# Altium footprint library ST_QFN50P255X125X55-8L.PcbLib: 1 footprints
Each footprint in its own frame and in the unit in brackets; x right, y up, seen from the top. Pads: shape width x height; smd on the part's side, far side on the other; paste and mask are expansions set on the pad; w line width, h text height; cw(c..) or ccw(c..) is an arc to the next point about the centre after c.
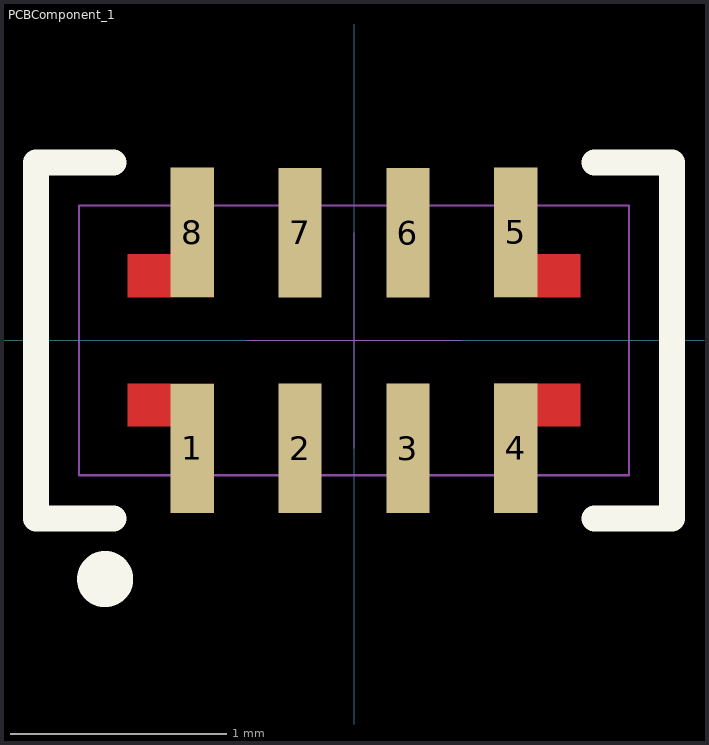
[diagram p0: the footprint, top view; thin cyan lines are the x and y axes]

## PCBComponent_1 [mm]
pads (8):
  rect 0.2x0.6 smd paste-20 mask+0.025: 1(-0.75,-0.501) 2(-0.25,-0.5) 3(0.25,-0.5) 4(0.75,-0.5) 5(0.75,0.5) 6(0.25,0.5) 7(-0.25,0.5) 8(-0.75,0.501)
Top Layer:
  rectangle: 0.65,0.2 1.05,0.4
  rectangle: 0.65,-0.4 1.05,-0.2
  rectangle: -1.05,-0.4 -0.65,-0.2
  rectangle: -1.05,0.2 -0.65,0.4
Top Overlay:
  circle w0.2: c-1.154,-1.106 r0.03
  lines w0.12: -1.115,-0.825 -1.475,-0.825 -1.475,0.825 -1.115,0.825 ; 1.115,-0.825 1.475,-0.825 1.475,0.825 1.115,0.825
Top Paste:
  rectangle: 0.68,-0.37 1.02,-0.23
  rectangle: 0.68,-0.77 0.82,-0.23
  rectangle: 0.16,-0.785 0.34,-0.215
  rectangle: -0.34,-0.785 -0.16,-0.215
  rectangle: -0.82,-0.77 -0.68,-0.23
  rectangle: -1.02,-0.37 -0.68,-0.23
  rectangle: 0.68,0.23 1.02,0.37
  rectangle: 0.68,0.23 0.82,0.77
  rectangle: 0.16,0.215 0.34,0.785
  rectangle: -0.34,0.215 -0.16,0.785
  rectangle: -1.02,0.23 -0.68,0.37
  rectangle: -0.82,0.23 -0.68,0.77
Top Solder:
  rectangle: 0.625,-0.425 1.075,-0.175
  rectangle: 0.625,0.175 1.075,0.425
  rectangle: -1.075,-0.425 -0.625,-0.175
  rectangle: -1.075,0.175 -0.625,0.425
Mechanical 15:
  lines w0.001: -0.5,0 0.5,0 ; 0,-0.5 0,0.5
  lines w0.01: -1.275,-0.625 -1.275,0.625 1.275,0.625 1.275,-0.625 -1.275,-0.625
3D body: height 1.45, standoff -1.45, extent -1.275,0.625 -1.275,0.625
3D body: height 0.55, standoff 0.05, extent -1.275,-0.625 1.275,0.625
